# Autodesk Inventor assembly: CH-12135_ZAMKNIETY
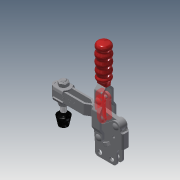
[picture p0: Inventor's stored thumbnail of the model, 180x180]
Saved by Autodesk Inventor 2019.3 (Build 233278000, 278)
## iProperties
Company: Î¢ÈíÖÐ¹ú
Created: 2012-09
Part Number: CH-12135_ZAMKNIETY
Material: Ogólny
Description: STEP AP203
Document SubType Name: Assembly
Designer: CADENGINEERING4
Sending System: SolidWorks 2010
Preprocessor: SwSTEP 2.0
Title: CH-12135.STEP
Author: Î¢ÈíÓÃ»§
Revision Number: ÈÎºÎ
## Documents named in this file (12)
- D:\Vault_2016\Projekty\STRONA\Vertical toggle clamp\Do zrobienia 3\CH-12135\CH-12135_ZAMKNIETY.iam
- D:\Vault_2016\Projekty\STRONA\Vertical toggle clamp\Do zrobienia 3\CH-12135\CH-12130-05.ipt
- D:\Vault_2016\Projekty\STRONA\Vertical toggle clamp\Do zrobienia 3\CH-12135\CH-12130-04 CONNECTING-PLATE.ipt
- D:\Vault_2016\Projekty\STRONA\Vertical toggle clamp\Do zrobienia 3\CH-12135\CH-12130-08.ipt
- D:\Vault_2016\Projekty\STRONA\Vertical toggle clamp\Do zrobienia 3\CH-12135\CH-FW-516.ipt
- D:\Vault_2016\Projekty\STRONA\Vertical toggle clamp\Do zrobienia 3\CH-12135\CH-FC-56212 Nut.ipt
- D:\Vault_2016\Projekty\STRONA\Vertical toggle clamp\Do zrobienia 3\CH-12135\CH-12130-03 STRAIGHT HANDLE.ipt
- D:\Vault_2016\Projekty\STRONA\Vertical toggle clamp\Do zrobienia 3\CH-12135\CH-FC-56212 SPINDLE SUPPLIED.ipt
- D:\Vault_2016\Projekty\STRONA\Vertical toggle clamp\Do zrobienia 3\CH-12135\CH-12130-06.ipt
- D:\Vault_2016\Projekty\STRONA\Vertical toggle clamp\Do zrobienia 3\CH-12135\CH-12130-07.ipt
- D:\Vault_2016\Projekty\STRONA\Vertical toggle clamp\Do zrobienia 3\CH-12135\CH-12135-02 SHORT U-BAR.ipt
- D:\Vault_2016\Projekty\STRONA\Vertical toggle clamp\Do zrobienia 3\CH-12135\CH-12135-01 STRAIGHT BASE.ipt
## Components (16 placed, 16 different names)
1. CH-12130-05_1
2. CH-12130-04 CONNECTING-PLATE_2
3. CH-12130-08_3
4. CH-FW-516_4
5. CH-FC-56212 Nut_5
6. CH-FW-516_6
7. CH-12130-03 STRAIGHT HANDLE_7
8. CH-FC-56212 SPINDLE SUPPLIED_8
9. CH-12130-06_9
10. CH-FC-56212 Nut_10
11. CH-12130-08_11
12. CH-12130-06_12
13. CH-12130-07_13
14. CH-12135-02 SHORT U-BAR_14
15. CH-12135-01 STRAIGHT BASE_15
16. CH-12130-05:2
